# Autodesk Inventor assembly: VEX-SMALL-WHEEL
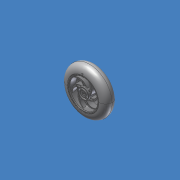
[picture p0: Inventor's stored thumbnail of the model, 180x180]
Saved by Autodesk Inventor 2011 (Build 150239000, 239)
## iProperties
Created: 2007-08
Part Number: VEX-SMALL-WHEEL
Document SubType Name: Assembly
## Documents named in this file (4)
- C:\Data Folder\VEX 2011\Inventor Datasets\Unit 6\Components\VEX-SMALL-WHEEL.iam
- C:\Data Folder\VEX 2011\Inventor Datasets\Unit 6\Components\SMALL-WHEEL-RIM.ipt
- C:\Data Folder\VEX 2011\Inventor Datasets\Unit 6\Components\SMALL-WHEEL-HUB.ipt
- C:\Data Folder\VEX 2011\Inventor Datasets\Unit 6\Components\SMALL-WHEEL-TIRE.ipt
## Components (3 placed, 3 different names)
1. SMALL-WHEEL-RIM — Insert:1, Mate:2
2. SMALL-WHEEL-HUB — Insert:1, Mate:1, Mate:3
3. SMALL-WHEEL-TIRE — Mate:1, Mate:2, Mate:3
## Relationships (4: Mate 3, Insert 1)
- Insert:1: SMALL-WHEEL-RIM ↔ SMALL-WHEEL-HUB
- Mate:1: SMALL-WHEEL-HUB ↔ SMALL-WHEEL-TIRE
- Mate:2: SMALL-WHEEL-RIM ↔ SMALL-WHEEL-TIRE
- Mate:3: SMALL-WHEEL-HUB ↔ SMALL-WHEEL-TIRE
